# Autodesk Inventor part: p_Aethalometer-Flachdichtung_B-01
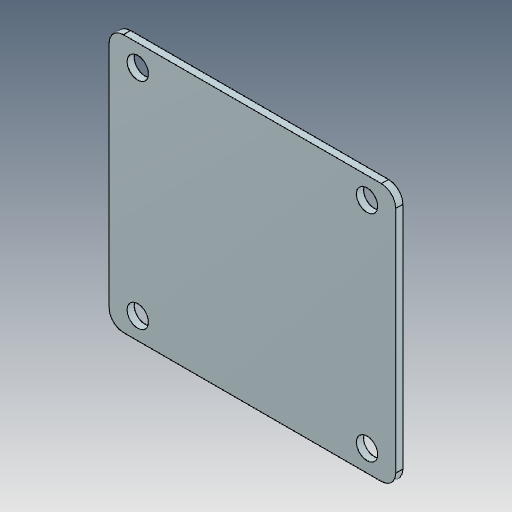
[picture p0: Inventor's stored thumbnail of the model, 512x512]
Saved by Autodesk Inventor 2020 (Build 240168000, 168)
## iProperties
Created: 2020-07
Part Number: p_Aethalometer-Flachdichtung_B-01
Material: Generisch
Document SubType Name: Modeling
Designer: Joshua Backlund
Density: 1 g/cm^3
Appearance: Vorgabe
Author: Joshua Backlund
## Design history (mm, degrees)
feature "Basis1"
feature "Basis2"
node "Volumenkörper1"
node "Volumenkörper2"
